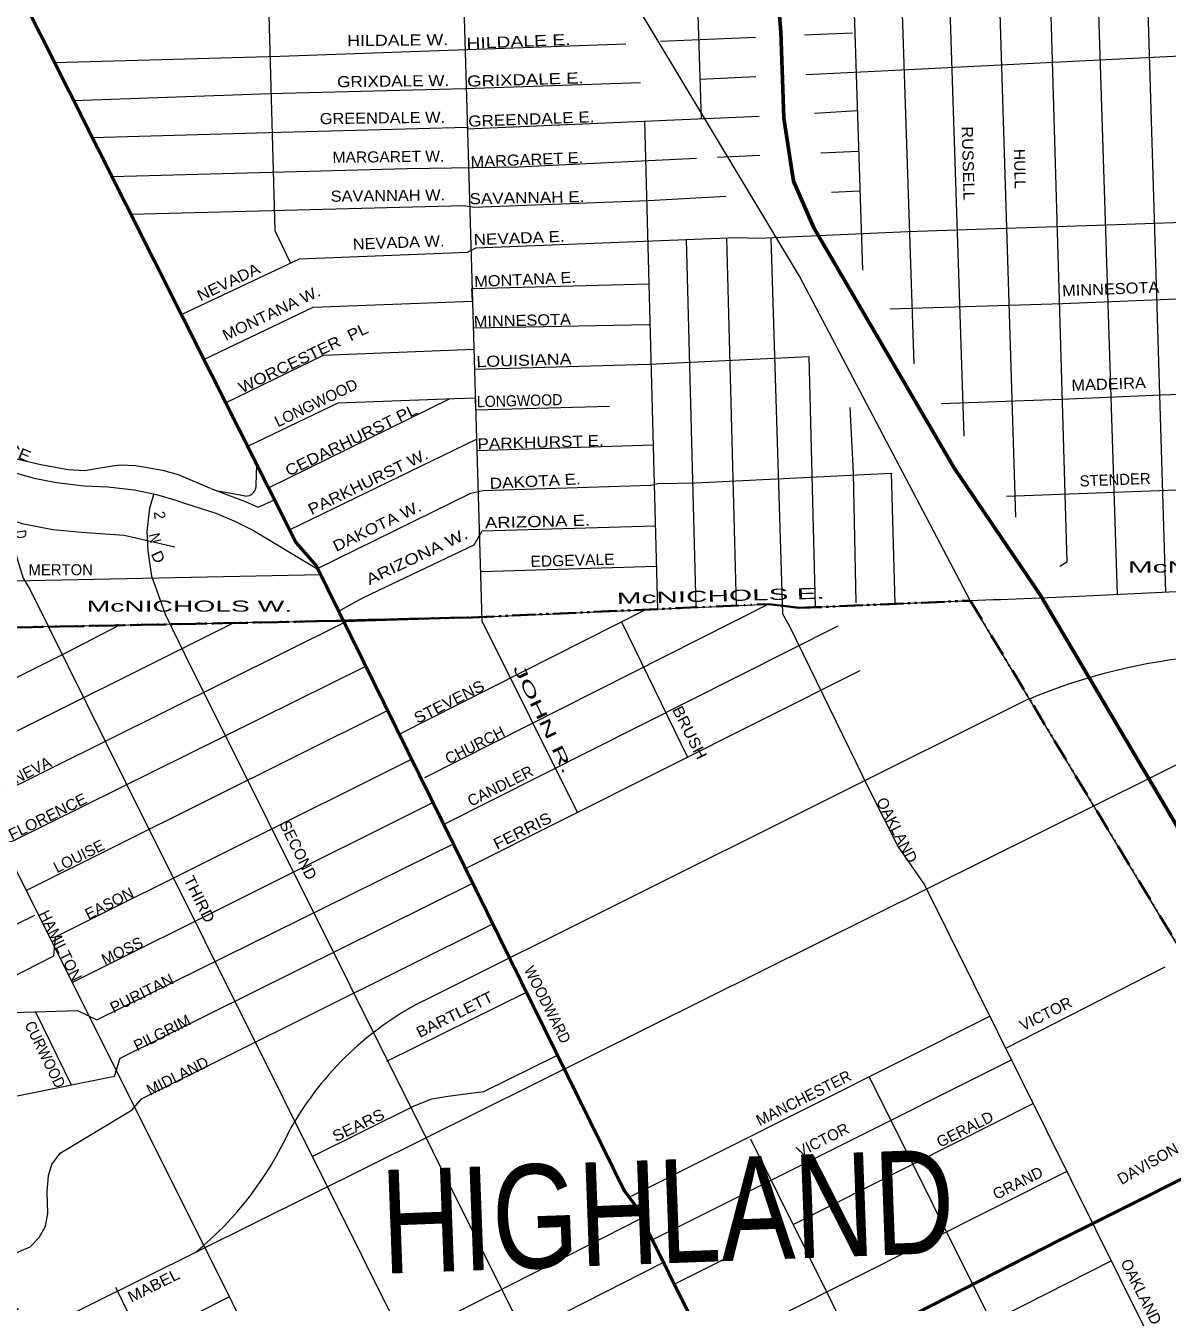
# Model space of a CAD drawing. Extents: x 34705 to 138605, y 34275 to 143551.
# Drawn here: x 82043 to 89751, y 126812 to 135435 of the extents above; entities that cross this region are included whole.
import ezdxf
from ezdxf.enums import TextEntityAlignment as Align

# ---------------------------------------------------------------- set-up
doc = ezdxf.new("R2010")
doc.units = 0
doc.header["$LTSCALE"] = 30
doc.linetypes.add('DASH_DOUBLE_DOT', pattern=[9.2, 5, -1.2, 0.3, -1.2, 0.3, -1.2])
for name, color, linetype, lineweight in [('1', 7, 'Continuous', 13), ('11', 7, 'Continuous', 13), ('50', 7, 'Continuous', 13), ('51', 7, 'Continuous', 35), ('59', 7, 'DASH_DOUBLE_DOT', 106)]:
    doc.layers.add(name, color=color, linetype=linetype, lineweight=lineweight)
doc.layers.add('12', color=7, linetype='Continuous')

msp = doc.modelspace()

# ---------------------------------------------------------------- linework, layer by layer
at = {"layer": '1'}
for p, q in [((87300.78, 135372.32), (87625.72, 135386.89)), ((86329.2, 135328.73), (86970.21, 135357.49)), ((86594.57, 135073), (86972.56, 135090.39)), ((86221.11, 134789.31), (86307.77, 131494.81)), ((87367.91, 134843.99), (87657.25, 134860.37)), ((86712.93, 134546.5), (86999.51, 134558.81)), ((87410.46, 134576.47), (87665.97, 134587.44)), ((87483.61, 134310.28), (87674.54, 134319.52)), ((86502.01, 133993.64), (86567.44, 131506.39)), ((86775.28, 133999.97), (86840.56, 131518.57)), ((85064.28, 133393.36), (86252.18, 133416.77)), ((87329.54, 133201.11), (87374.02, 131510.11)), ((83682.3, 132313.25), (84904.36, 132915.36)), ((83599.13, 132331.68), (83604.11, 132468.76)), ((87886.82, 132411.78), (87909.98, 131531.56)), ((83528.11, 132257.4), (83343.25, 132289.97)), ((85118.46, 131749.08), (86298.69, 131783.98)), ((81011.87, 131665.28), (84034.97, 131727.21)), ((84737.51, 130356.91), (87059.05, 131528.96)), ((84568.69, 130652.44), (86229.31, 131491.3)), ((84864.12, 130040.27), (87528.3, 131380.71)), ((86065.06, 131408.34), (86511.64, 130495.2)), ((85012.71, 129742.51), (87676.02, 131079.9)), ((82047.33, 129593.23), (84476.37, 130805.48)), ((82357.48, 128972.58), (84793.17, 130188.16)), ((88659.58, 128528.59), (89734.57, 129077.86)), ((84480.93, 128441.55), (85424.11, 128907.42)), ((82110.83, 128775.34), (82350.66, 128281.82)), ((86116.41, 127524.1), (88551.47, 128745.95)), ((86272.99, 127234.66), (88698.73, 128449.88)), ((87736.46, 128336.85), (90276.5, 123250.15)), ((87224.14, 127338.2), (88844.63, 128156.54)), ((86421.25, 126936.68), (86795, 127123.61)), ((82649.4, 126914.57), (85555.36, 121071.24)), ((82828.45, 126554.54), (83417.61, 126851.16))]:
    msp.add_line(p, q, dxfattribs=at)
for points in [[(87464.75, 142129.63), (87514.19, 140589.35), (87575.42, 138090.45), (87593.79, 136845.61), (87691.68, 133783.23)], [(88507.22, 142159.37), (88555.06, 140668.97), (88591.47, 139538.15), (88616.29, 138170.07), (88643.69, 136882.81), (88579.55, 136821.11), (88725.1, 132115.05)], [(88507.22, 142159.37), (88555.06, 140668.97), (88591.47, 139538.15), (88616.29, 138170.07), (88643.69, 136882.81), (88579.55, 136821.11), (88720.65, 132259.05)], [(88777.36, 142167.08), (88824.46, 140699.59), (88861.2, 139542.02), (88867.32, 139474.64), (88885.69, 138200.7), (89070.95, 131812.26), (89025.2, 131781.21)], [(89101.37, 142176.32), (89148.97, 140693.47), (89210.2, 138194.57), (89234.69, 136961.98), (89234.69, 136833.36), (89246.93, 136710.87), (89410.75, 131593.51)], [(89431.5, 142185.73), (89479.6, 140687.34), (89540.83, 138188.45), (89595.93, 136049.39), (89608.18, 135908.52), (89738.51, 131609.03)], [(84837.33, 142054.69), (84972.87, 136739.69), (84968.79, 136641.55), (85122.42, 131415.98), (85765.27, 130123.3)], [(83600.48, 139335.93), (83613.68, 138094.29), (83725.2, 134050.56), (83830.15, 133834.02)], [(87850.97, 137739.35), (87863.19, 136894.61), (87861.91, 136851.12), (87918.3, 136796.61), (88038.01, 133150.06)], [(88242.65, 136838.75), (88261.17, 136165.76), (88376.73, 132662.85)], [(86549.73, 136758.75), (86549.73, 136495.37), (86602.99, 134805.88)], [(82238.39, 135184.9), (83761.61, 135227.37), (86095.2, 135312.74)], [(87311.86, 135105.07), (87957.11, 135136.8), (89335.02, 135206.59), (90294.33, 135253.12), (92906.24, 135253.12), (92999.26, 135253.12), (93505.08, 135264.75), (93592.29, 135276.38), (93691.12, 135311.28), (93842.29, 135317.1), (95637.14, 135363.58)], [(82367.34, 134928.44), (83694.04, 134975.42), (85007.99, 135010.31), (86194.04, 135051.02)], [(82492.66, 134679.21), (83682.41, 134713.71), (85024.45, 134748.37), (85024.77, 134737.39), (86993.94, 134822.85)], [(83101.01, 133486.56), (83891.71, 133858.78), (85025.43, 133905.3), (85083.57, 133934.38), (86840.83, 134002.71), (86990.55, 133998.36), (87997.81, 134043.42), (88660.6, 134066.69), (89340.84, 134089.95), (89858.28, 134107.4), (90311.77, 134159.74), (90515.26, 134258.61), (90840.84, 134305.14), (93673.68, 134351.66), (95138.8, 134363.3), (95679.5, 134380.74), (97726.73, 134441.09), (98308.13, 134452.72), (100831.39, 134522.51), (103555.22, 134615.57), (106139.42, 134688.42)], [(82625.64, 134414.74), (84618.46, 134469.44), (85368.46, 134481.07), (86571.95, 134539.23)], [(82753.19, 134161.08), (85002.18, 134219.36), (85071.94, 134207.73), (86246.36, 134254.25), (86769.62, 134283.33)], [(79747.26, 134060.41), (80223.95, 133881.6), (80302.66, 133822.54), (80368.26, 133730.67), (80525.69, 133533.82), (80689.69, 133330.4), (80807.76, 133192.6), (80971.76, 133041.68), (81207.91, 132864.51), (81332.54, 132785.77), (81476.85, 132700.46), (81706.44, 132602.04), (81850.76, 132542.98), (81981.95, 132510.17), (82145.95, 132470.8), (82329.62, 132437.99), (82441.13, 132431.43)], [(87073.88, 134002.08), (87152.65, 131463.56), (87198.57, 131378.26), (87736.46, 130275.87), (87933.26, 129888.72), (88110.37, 129632.8), (91078.81, 123654.49)], [(83247.05, 133178.88), (83984.73, 133533.09), (85059.01, 133572.84), (85056.46, 133659.62), (86252.18, 133690.12)], [(87877.52, 133521.98), (89044.32, 133557.81), (90305.95, 133610.15), (90364.09, 133435.68), (91976, 133444.39), (92516.7, 133456.02), (93417.87, 133473.47), (94249.26, 133502.55), (94598.1, 133671.21), (95685.31, 133694.47)], [(83393.68, 132887.27), (84054.5, 133208.86), (85068.5, 133250.14)], [(80674.16, 133171.13), (80781.52, 133153.23), (80912.72, 133028.56), (81148.87, 132818.58), (81325.98, 132700.46), (81509.65, 132588.91), (81634.29, 132542.98), (81745.8, 132490.48), (81916.36, 132431.43), (82100.03, 132378.93), (82252.06, 132349.43), (82438.63, 132327.32), (82598.57, 132319.88), (82775.68, 132300.19), (82926.55, 132267.38), (83064.31, 132228.01), (83123.35, 132208.32), (83326.7, 132142.71), (83464.45, 132083.65), (83582.53, 132024.59), (84016.92, 131763.87)], [(85072.48, 133114.7), (86252.18, 133149.24), (87329.54, 133201.11)], [(83548.69, 132596.74), (84153.34, 132887.53), (84938.22, 132916.61), (85078.17, 132921.27), (85080.55, 132840.15), (85984.74, 132864.27)], [(88224.01, 132883.53), (89032.7, 132912.25), (89707.12, 132941.33), (90358.28, 132964.59)], [(87607.06, 132856.1), (87628.46, 132415.09), (87648.11, 131537.13)], [(83824.35, 132030.75), (85086.35, 132642.89), (85088.63, 132565.44), (86278.63, 132602.83)], [(88664.35, 132256.06), (90364.09, 132319.03), (90401.88, 132580.75), (92000.72, 132586.56), (93441.55, 132615.62)], [(81009.47, 132498.69), (81101.31, 132459.32), (81180.02, 132426.51), (81317.78, 132347.77), (81442.41, 132282.15), (81599.85, 132209.97), (81770.4, 132150.91), (81901.59, 132111.54), (82019.67, 132072.17), (82227.19, 132032.89), (82419.81, 132013.11), (82708.44, 131993.43), (83049.55, 131914.69)], [(82440.97, 132430.29), (82644.37, 132464.11), (82683.54, 132467.6), (82786.4, 132463.55), (82967.61, 132431.79), (83073.19, 132402.35), (83289.91, 132311.38)], [(80637.21, 132415.02), (86234.97, 121213.34)], [(81979.6, 132413.35), (81949.15, 132306.75), (81942.59, 132188.64), (81949.15, 132024.59), (81962.27, 131932.73), (81988.51, 131827.74), (82027.87, 131703.06), (82073.79, 131624.32), (82716.64, 130325.07), (82716.64, 130325.07), (85912.86, 123919.09), (85958.78, 123794.41), (86385.16, 122947.93), (86444.2, 122862.63), (87053.1, 121625.65)], [(84014.04, 131769.7), (85048.69, 132278.32), (85130.08, 132295.77), (86263.81, 132330.67), (86310.32, 132342.3), (86566.13, 132348.11), (87886.82, 132411.78)], [(83292.64, 132308.52), (83526.39, 132220.46), (83612.51, 132183.21), (83723.01, 132232.28)], [(82908.35, 132272.58), (82880.64, 132175.52), (82860.96, 132018.03), (82867.52, 131886.79), (82893.76, 131716.19), (82926.55, 131624.32), (82985.59, 131460.27), (83116.79, 131191.24), (87021.45, 123361.33), (87073.93, 123269.46), (87651.19, 122140.82), (87769.26, 122127.7), (87835.83, 122020.12)], [(84157.07, 131479.37), (84240.55, 131528.08), (84327.76, 131574.6), (85071.94, 131929.37), (85124.27, 132022.43), (86292.88, 132057.32)], [(79721.13, 131315.9), (81105.26, 131349.05), (81242.43, 131359.6), (84006.84, 131412.38), (84265.35, 131412.38), (85051.41, 131438.76), (87062.73, 131528.48), (87263.2, 131502.09), (88576.82, 131560.14), (88624.3, 131560.14), (89151.86, 131581.25), (90043.44, 131623.47)], [(79736.69, 130733.66), (80110.82, 130742.16), (81086.8, 130768.54), (81176.49, 130763.27), (81366.41, 130847.7), (81503.57, 130794.93), (82318.65, 131201.28), (82674.38, 131386.94)], [(79752.4, 130145.95), (80211.05, 130156.38), (81187.04, 130182.76), (81213.42, 130188.04), (81590.62, 130378.02), (81659.2, 130509.95), (83447.51, 131401.7)], [(79760.15, 129855.98), (80221.61, 129866.12), (81139.56, 129881.95), (81223.97, 129887.23), (81711.96, 130135.27), (81801.64, 130214.43), (84194.57, 131403.24)], [(79767.88, 129566.7), (81213.42, 129591.7), (81828.02, 129897.79), (81959.91, 129929.45), (84339.52, 131109.01)], [(81452.18, 128754.44), (82234.24, 129153.69), (82244.79, 129280.34), (84649.24, 130480.3)], [(79790.99, 128701.73), (82392.51, 128784.27), (82524.4, 128720.95), (84930.89, 129908.6)], [(81356.85, 127947.25), (81483.53, 128106.04), (82643.94, 128341.28), (82682.49, 128460.83), (85061.7, 129643.06)], [(79783.14, 128995.82), (80242.71, 129005.92), (81181.76, 129027.03), (81245.07, 129005.92), (82104.99, 129428.11)], [(81840.66, 127077.59), (82000.13, 127157.35), (82073.37, 127188.21), (82135.06, 127249.91), (82177.46, 127327.04), (82192.89, 127411.88), (82189.03, 127558.42), (82196.74, 127670.26), (82219.87, 127743.53), (82277.7, 127820.66), (82763.45, 128113.75), (82825.13, 128187.02), (85196.59, 129369.26)], [(83977.36, 127798.29), (84665.98, 128140.74), (84785.49, 128187.02), (84893.44, 128206.3), (85136.31, 128237.16), (85633.7, 128481.98)], [(86936.18, 127916.89), (87670.87, 126440.47), (87893.9, 125987.7), (87966.05, 125935.21), (88221.88, 125410.26), (88235, 125331.52), (89474.59, 122846.01)], [(83098.86, 124557.51), (83251.13, 124634.29), (83428.47, 124715.28), (83698.33, 124857.96), (84218.78, 125142.37), (84253.48, 125277.35), (89073.41, 127698.22)], [(82605.98, 125544.71), (83218.36, 125852.92), (83765.8, 126119.02), (83827.48, 126173.01), (86200.14, 127381.1)], [(83304.56, 125597.18), (83671.34, 125770.97), (83883.38, 125878.95), (83975.9, 125875.1), (86346.84, 127082.16)], [(83910.07, 124391.86), (84466.08, 124665.61), (84565.99, 124700.38), (86902.99, 125873.6), (87002.9, 125890.98), (89371.24, 127093.46)]]:
    msp.add_lwpolyline(points, dxfattribs=at)
at = {"layer": '1', "lineweight": 53}
msp.add_lwpolyline([(78887.63, 141884.98), (81376.82, 136898.39), (83869.51, 131940.93), (84007.27, 131783.45), (86083.41, 127569.11), (86155.57, 127470.68), (88660.55, 122435.75)], dxfattribs=at)
at = {"layer": '1'}
msp.add_arc((83528.19, 132328.78), 71.25, 266.51742, 4.65495, dxfattribs=at)
at = {"layer": '50'}
msp.add_line((84719.59, 128844.52), (88813.16, 130887.5), dxfattribs=at)
for points in [[(92780.96, 124298.93), (88419.69, 131551.9), (87267.07, 133743.51), (82340.87, 141938.99)], [(82079.69, 126598.83), (92308.42, 131685.49), (94831.66, 132923.4)]]:
    msp.add_lwpolyline(points, dxfattribs=at)
for centre, radius, start, end in [((90325.44, 127295.77), 3894.5, 94.76093, 112.79656), ((85714.11, 126927.28), 2159.83, 117.41712, 151.56255), ((81719.19, 128941.36), 2317.6, 309.46074, 335.43634)]:
    msp.add_arc(centre, radius, start, end, dxfattribs=at)
at = {"layer": '51', "lineweight": 60}
for points in [[(86901.01, 142113.55), (86991.94, 138514.25), (87042.78, 136476.8), (87088.69, 136004.35), (87141.17, 135394.1), (87160.85, 134810.09), (87226.45, 134383.57), (87364.2, 134068.6), (88313.72, 132444.55), (88890.98, 131591.51), (89832.29, 130000.27), (90029.08, 129869.03), (90337.39, 129435.95), (90835.93, 128622.28), (91261.11, 128074.43), (91760.85, 127500.2), (92062.6, 127277.1), (92213.47, 127198.36), (92521.78, 126958.86), (92666.09, 126807.93)], [(95130.25, 130321.18), (94082.22, 129796.99), (93888.4, 129689.28), (93608.45, 129481.05), (93098.79, 129014.3), (92072.28, 128418.31), (91058.35, 127996.45), (90362.06, 127903.1), (89026.89, 127235.3), (85010.62, 125185.23), (84436.35, 124933.9), (84307.14, 124933.9), (84098.97, 124919.54), (83190.65, 124373.65)]]:
    msp.add_lwpolyline(points, dxfattribs=at)
at = {"layer": '59', "lineweight": 35}
for points in [[(92674.01, 124470.72), (85052.76, 120629.83), (79713.12, 131324.76), (84006.84, 131412.38), (85051.41, 131438.76), (87061.1, 131528.41), (87260.49, 131502.45), (88419.69, 131551.9), (91983.3, 125629.39)], [(84141.44, 131415.18), (85059.19, 131438.36), (86456.23, 131500.68)], [(87137.57, 131518.45), (87260.49, 131502.45), (88419.69, 131551.9), (91983.3, 125629.39), (91989.11, 125632.28)], [(87141.48, 131518.55), (87268.27, 131502.05), (88420.12, 131551.18)], [(79713.12, 131324.76), (84006.84, 131412.38), (85051.41, 131438.76), (86415.72, 131499.62)], [(81185.94, 131354.26), (84014.62, 131411.98), (84014.65, 131411.98)]]:
    msp.add_lwpolyline(points, dxfattribs=at)

# ---------------------------------------------------------------- texts
at = {"layer": '11'}
for s, rotation, width, p in [('HILDALE W.', 0.676, 1.2, (84554.9, 135299.2)), ('HILDALE E.', 2.25, 1.3, (85371.75, 135290.47)), ('GRIXDALE W.', 0.674, 1.15, (84524.79, 135022.62)), ('GRIXDALE E.', 1.698, 1.25, (85417.99, 135033.3)), ('GREENDALE W.', 0.676, 1.1, (84452.31, 134774)), ('GREENDALE E.', 2.114, 1.15, (85458.58, 134766.73)), ('RUSSELL', 271.394, 1.1, (88368.5, 134502.61)), ('MARGARET W.', 0.675, 1.05, (84492.85, 134512.02)), ('MARGARET E.', 2.267, 1.1, (85428.2, 134492.47)), ('HULL', 271.392, 1.05, (88717.2, 134466.92)), ('SAVANNAH W.', 0.676, 1.1, (84489.25, 134249.42)), ('SAVANNAH E.', 1.136, 1.15, (85428.25, 134235.42)), ('NEVADA W.', 2.228, 1.1, (84562.77, 133932.97)), ('NEVADA E.', 2.228, 1.15, (85376.36, 133963.28)), ('NEVADA', 25.561, 1.1, (83428.56, 133668.99)), ('MONTANA E.', 2.514, 1.1, (85416.01, 133683.87)), ('MONTANA W.', 25.605, 1.1, (83717.9, 133459.07)), ('MINNESOTA', 2.229, 1.1, (89369.29, 133619.24)), ('MINNESOTA', 1.486, 1.1, (85397.42, 133406.76)), ('WORCESTER  PL', 25.64, 1.15, (83933.76, 133157.18)), ('LOUISIANA', 1.782, 1.2, (85408.1, 133137.42)), ('MADEIRA', 2.228, 1.1, (89355.11, 132977.34)), ('LONGWOOD', 1.528, 0.95, (85378.92, 132864.95)), ('PLAISANCE', 336.796, 1.2, (81748.17, 132618.16)), ('CEDARHURST PL', 25.994, 1.15, (84257.05, 132602.56)), ('PARKHURST E.', 1.644, 1.15, (85520.86, 132584.23)), ('PARKHURST W.', 25.866, 1.15, (84370.6, 132321.24)), ('DAKOTA E.', 2.979, 1.15, (85485.27, 132321.26)), ('DAKOTA W.', 25.853, 1.15, (84431.63, 132021.05)), ('2', 277.497, 0.95, (82911.61, 132123.72)), ('ARIZONA E.', 1.463, 1.25, (85499.63, 132048.76)), ('D', 278.128, 0.8, (81975.06, 131994.04)), ('ARIZONA W.', 25.463, 1.25, (84699.48, 131815.41)), ('N', 283.38, 0.9, (82880.3, 131966.14)), ('D', 294.278, 1.1, (82903.8, 131831.47)), ('EDGEVALE', 1.567, 1.05, (85736.01, 131786.58)), ('McNICHOLS E.', 1.45, 2, (86736.59, 131546.97)), ('JOHN R.', 295.456, 2, (85504.45, 130736.12))]:
    msp.add_text(s, height=75, rotation=rotation, dxfattribs=dict(at, width=width)).set_placement(p, align=Align.CENTER)
for s, rotation, p in [('LONGWOOD', 25.838, (84019.97, 132853.74)), ('STENDER', 2.229, (89399.16, 132330.93))]:
    msp.add_text(s, height=75, rotation=rotation, dxfattribs=at).set_placement(p, align=Align.CENTER)
msp.add_text('MERTON', height=75, dxfattribs=at).set_placement((82280.38, 131722.83), align=Align.CENTER)
for s, width, p in [('McNICHOLS E.', 2, (90185.76, 131741.38)), ('McNICHOLS W.', 1.9, (83149.1, 131477.05))]:
    msp.add_text(s, height=75, dxfattribs=dict(at, width=width)).set_placement(p, align=Align.CENTER)
at = {"layer": '12'}
for s, rotation, width, p in [('STEVENS', 26.711, 1.1, (84918.9, 130834.85)), ('BRUSH', 296.711, 1.1, (86492.53, 130643.49)), ('FLORENCE', 26.464, 1.05, (82208.06, 130060.34)), ('FERRIS', 26.709, 1.15, (85413.42, 129963.9)), ('THIRD', 296.464, 1.1, (83182.52, 129518.99)), ('PURITAN', 26.624, 1.05, (82843.94, 128866.36)), ('BARTLETT', 26.624, 1.1, (84956.04, 128723.23)), ('CURWOOD', 296.183, 0.9, (82141.26, 128470.34)), ('SEARS', 25.626, 1.1, (84305.6, 127975.35))]:
    msp.add_text(s, height=75, rotation=rotation, dxfattribs=dict(at, width=width)).set_placement(p, align=Align.CENTER)
for s, rotation, p in [('CHURCH', 26.711, (85093.05, 130542.32)), ('GENEVA', 26.465, (82038.89, 130341.17)), ('CANDLER', 26.71, (85264.08, 130267.15)), ('OAKLAND', 297.083, (87891.83, 129984.86)), ('SECOND', 296.467, (83849.65, 129850.36)), ('LOUISE', 26.626, (82419.65, 129791.99)), ('EASON', 26.625, (82624.51, 129473.73)), ('MOSS', 25.621, (82711.3, 129153.17)), ('PILGRIM', 26.625, (82981.05, 128599.75)), ('MIDLAND', 26.624, (83085.35, 128308.07))]:
    msp.add_text(s, height=75, rotation=rotation, dxfattribs=at).set_placement(p, align=Align.CENTER)
for s, rotation, p in [('HAMILTON', 296.594, (82129.62, 129437.28)), ('VICTOR', 26.669, (88776.72, 128642.99)), ('MANCHESTER', 26.736, (86998.11, 128001.6)), ('GERALD', 26.734, (88216.44, 127856.06)), ('VICTOR', 26.737, (87271.48, 127790.96)), ('DAVISON', 29.724, (89440.98, 127604.67)), ('GRAND', 26.736, (88595.77, 127504.04)), ('OAKLAND', 296.736, (89432.15, 127081.76))]:
    msp.add_text(s, height=75, rotation=rotation, dxfattribs=at).set_placement(p)
for s, rotation, width, p in [('WOODWARD', 296.71, 0.9, (85405.19, 129060.01)), ('MABEL ', 26.434, 1.1, (82756.55, 126809.88))]:
    msp.add_text(s, height=75, rotation=rotation, dxfattribs=dict(at, width=width)).set_placement(p)
at = {"layer": '59', "width": 0.8}
msp.add_text('HIGHLAND', height=700, rotation=2.129, dxfattribs=at).set_placement((86389.94, 127077.51), align=Align.CENTER)

doc.saveas('drawing.dxf')
